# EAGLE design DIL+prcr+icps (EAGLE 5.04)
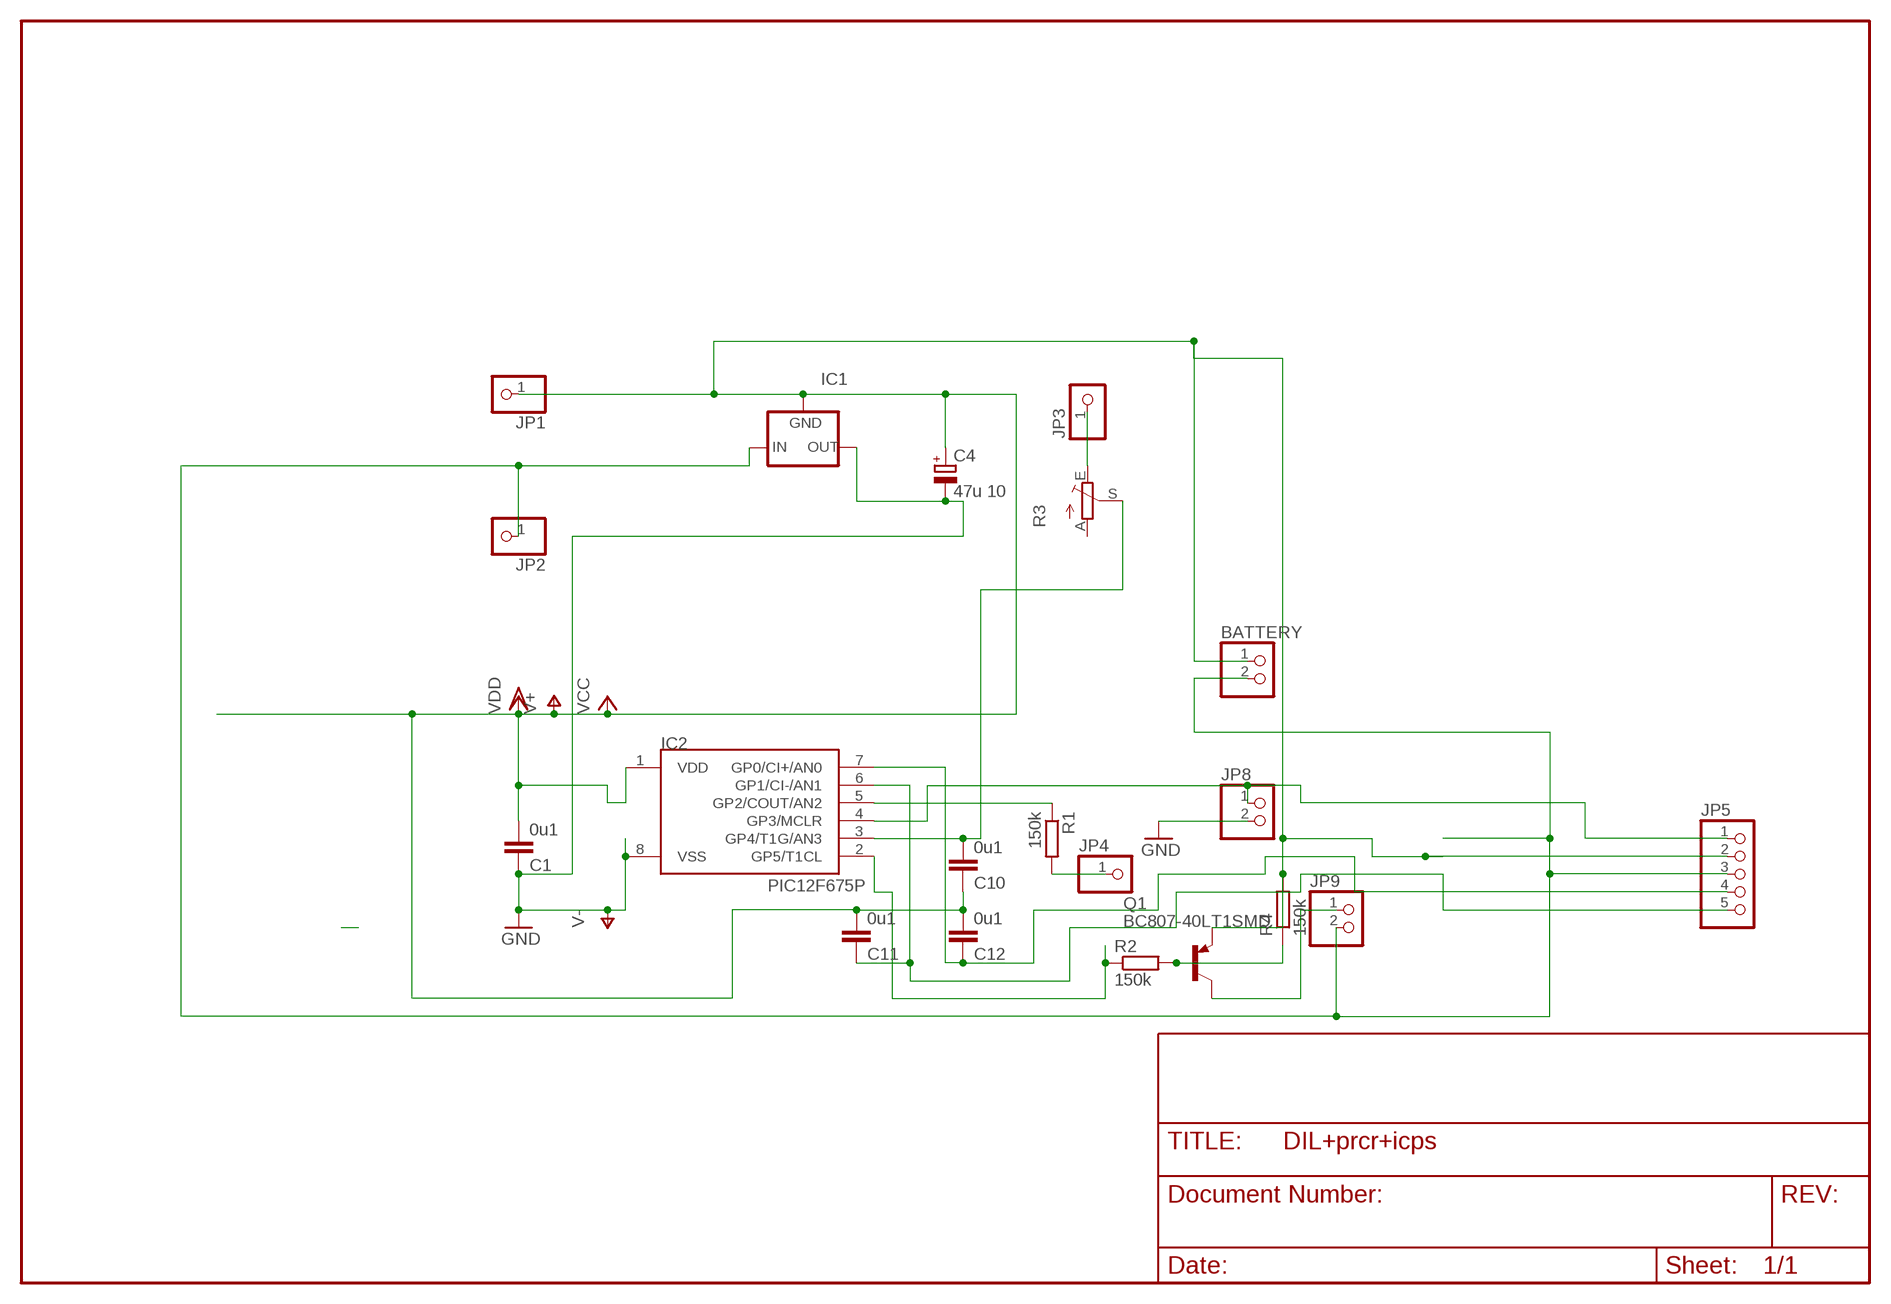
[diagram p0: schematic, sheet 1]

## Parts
BATTERY  PINHD-1X2  [1X02]
C1  0u1  C-EUC1206  [C1206]
C4  47u 10  CPOL-EUE2.5-6  [E2,5-6]
C10  0u1  C-EUC1206  [C1206]
C11  0u1  C-EUC1206  [C1206]
C12  0u1  C-EUC1206  [C1206]
IC1  79LXX  [79LXX]
IC2  PIC12F675P  [DIL8]
JP1  PINHD-1X1  [1X01]
JP2  PINHD-1X1  [1X01]
JP3  PINHD-1X1  [1X01]
JP4  PINHD-1X1  [1X01]
JP5  PINHD-1X5  [1X05]
JP8  PINHD-1X2  [1X02]
JP9  PINHD-1X2  [1X02]
Q1  BC807-40LT1SMD  [SOT23-BEC]
R1  150k  R-EU_R0805  [R0805]
R2  150k  R-EU_R0805  [R0805]
R3  TRIM_EU-CA6V  [CA6V]
R4  150k  R-EU_R0805  [R0805]

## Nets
GND: C1.1 C4.- IC1.OUT IC2.8(VSS) JP8.2 ; supply symbol labelled V-
N$1: JP3.1 R3.E
N$2: JP4.1 R1.2
N$3: IC2.4(GP3/MCLR) JP5.1 JP8.1
N$4: Q1.B R2.2 R4.1
N$5: IC2.5(GP2/COUT/AN2) R1.1
N$7: BATTERY.2 IC1.IN JP2.1 JP5.3 JP9.2
N$8: IC2.2(GP5/T1CL) R2.1
N$9: JP9.1 Q1.C
N$12: C10.2 IC2.3(GP4/T1G/AN3) R3.S
N$13: C12.1 IC2.7(GP0/CI+/AN0) JP5.4
N$15: C11.1 IC2.6(GP1/CI-/AN1) JP5.5
V+: BATTERY.1 C1.2 C4.+ C10.1 C11.2 C12.2 IC1.GND IC2.1(VDD) JP1.1 JP5.2 Q1.E R4.2 ; supply symbol labelled VCC, VDD
Unconnected: R3.A

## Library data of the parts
BATTERY JP8 JP9 = pinhead:PINHD-1X2: PIN HEADER
C1 C10-C12 = rcl:C-EU: CAPACITOR, European symbol
C4 = rcl:CPOL-EU: POLARIZED CAPACITOR, European symbol
IC1 = v-reg:79LXX: VOLTAGE REGULATOR
IC2 = microchip-3:PIC12F6*: uPC nW 1k Program Flash memory 2x Timer Comparator 10b A/D converter/ 4xIN
JP1-JP4 = pinhead:PINHD-1X1: PIN HEADER
JP5 = pinhead:PINHD-1X5: PIN HEADER
Q1 = transistor-pnp:BC807*: PNP Transistror
R1 R2 R4 = rcl:R-EU_: RESISTOR, European symbol
R3 = pot:TRIM_EU-: POTENTIOMETER

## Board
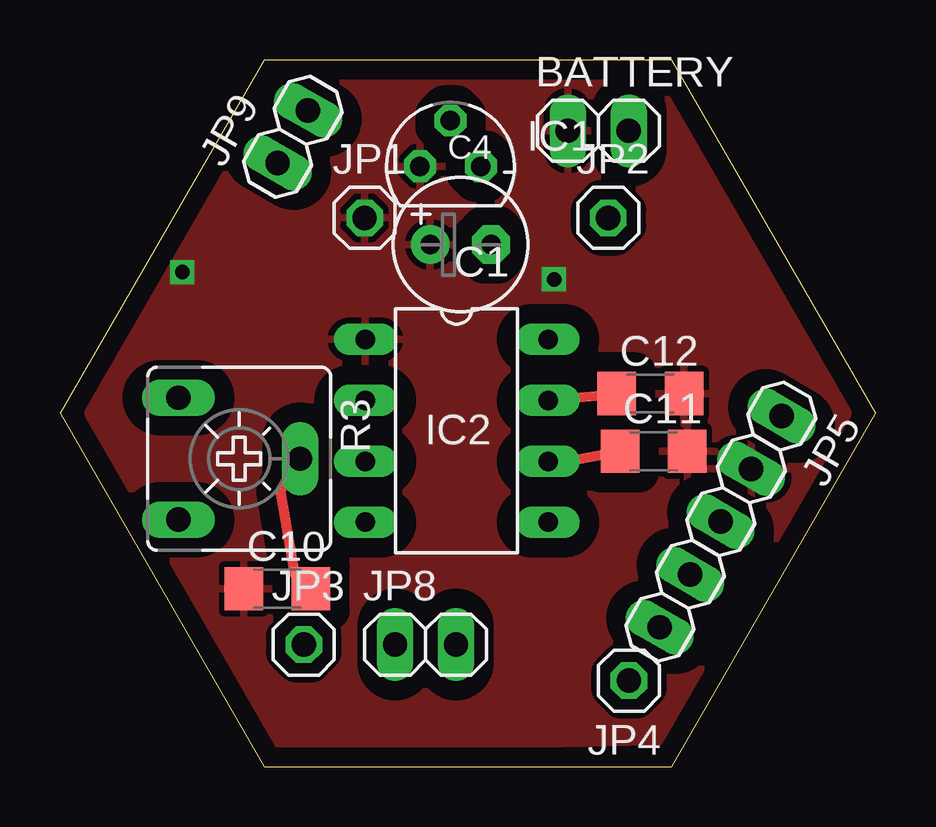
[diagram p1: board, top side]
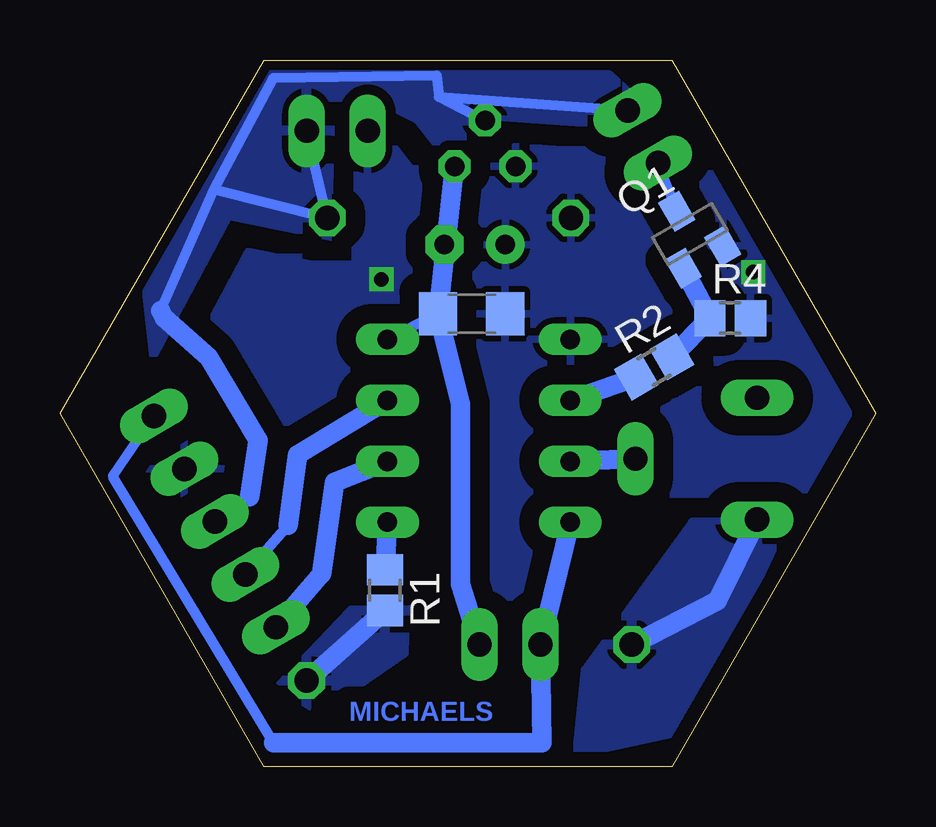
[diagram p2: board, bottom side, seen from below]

Size 34 x 29.44 mm. Coordinates in mm from the lower left corner, seen from the top.
Outline: 8.5,0 25.5,0 34,14.72 25.5,29.44 8.5,29.44 0,14.72 8.5,0
Copper layers (1*16): Top 0.035mm / dielectric 1.5mm / Bottom 0.035mm
Design rules "default *": minimum track width 10mil, minimum drill 24mil, track to track 8mil, track to pad 8mil, pad to pad 8mil, via to via 8mil, smd to smd 8mil, copper to edge 10mil, drill to drill 8mil, minimum pad ring 10mil, minimum via ring 8mil, stop-mask expansion 4mil, vias tented up to drill 0mil, thermal gap 10mil

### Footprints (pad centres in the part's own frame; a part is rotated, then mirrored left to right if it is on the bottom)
1X02 = drill 1.016 long: 1 -1.27,0; 2 1.27,0
C1206 = smd 1.6 x 1.8: 1 -1.4,0; 2 1.4,0
E2,5-6 = drill 0.813 pad 1.6 round: + -1.27,0 | drill 0.813 pad 1.6 octagon: - 1.27,0
79LXX = drill 0.813 octagon: GND -1.27,0; IN 0,1.905; OUT 1.27,0
DIL8 = drill 0.813 long: 1 -3.81,-3.81; 2 -1.27,-3.81; 3 1.27,-3.81; 4 3.81,-3.81; 5 3.81,3.81; 6 1.27,3.81; 7 -1.27,3.81; 8 -3.81,3.81
1X01 = drill 1.016 octagon: 1 0,0
1X05 = drill 1.016 long: 1 -5.08,0; 2 -2.54,0; 3 0,0; 4 2.54,0; 5 5.08,0
SOT23-BEC = smd 1 x 1.4: B -0.95,-1.1; C 0,1.1; E 0.95,-1.1
R0805 = smd 1.3 x 1.5: 1 -0.85,0; 2 0.85,0
CA6V = drill 1.016 long: A -2.54,-2.54; E 2.54,-2.54; S 0,2.54

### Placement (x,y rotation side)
BATTERY  22.44,26.49 0 top
C1  16.84,18.86 0 bottom
C4  16.7,21.75 0 top
C10  9.07,7.41 0 top
C11  24.75,13.14 0 top
C12  24.61,15.54 0 top
IC1  16.28,25.01 0 top
IC2  16.54,13.99 270 top
JP1  12.7,22.86 0 top
JP2  22.86,22.86 0 top
JP3  10.16,5.08 0 top
JP4  23.72,3.58 180 top
JP5  27.55,10.21 240 top
JP8  15.24,5.08 0 top
JP9  9.71,26.24 60 top
Q1  7.74,22.18 30 bottom
R1  20.45,7.35 270 bottom
R2  9.23,16.65 30 bottom
R3  7.47,12.83 270 top
R4  6.06,18.69 0 bottom

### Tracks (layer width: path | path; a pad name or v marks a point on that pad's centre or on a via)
GND
  Bottom 0.406: C1.1 IC2.8 | 18.07,20.35 C4.-
  Bottom 0.813: JP8.2 17.3,7.6 17.3,15.1 C1.1 18.07,20.35 IC1.OUT
N$1
  Bottom 0.813: JP3.1 6.6,6.9 R3.E
  pour Bottom (isolate 0.61): 5.08,10.16 7.62,10.16 12.1,4 12.45,0.55 7.85,1.55 3.7,10.35
N$2
  Bottom 0.813: JP4.1 R1.2
  pour Bottom (isolate 0.61): 22.86,2.54 19.65,4.75 19.6,6.65 21.85,6.5 24.85,3.35 23.3,2.4
N$3
  Bottom 0.406: JP5.1 31.8,12.1 25.1,1
  Bottom 0.813: IC2.4 JP8.1 13.9,1 25.1,1
N$4
  Bottom 0.813: Q1.B R4.1 R2.2
N$5
  Bottom 0.813: R1.1 IC2.5
N$7
  Bottom 0.406: 29.8,19 27.58,24.05 | 27.58,24.05 25.1,28.7 18.3,28.8 18.2,27.9 | 18.2,27.9 IC1.IN | 18.2,27.9 JP9.2 | 27.58,24.05 JP2.1 BATTERY.2 | 26.1,11.25 28,9.95 JP5.3
  Bottom 0.813: 29.8,19 29.65,18.7 27.8,17.05 25.75,13.6 26.1,11.25
  pour Bottom (isolate 0.406, rank 2): 10.16,27.94 11.1,28.8 25.2,29 30.45,20.35 30.1,17.2 27,23 22.6,22.1 22.8,24.1 22.7,27.9 20.9,27.9 19.1,27 18.2,25.85 16.9,25.85 17,27.2 11.3,26.8
N$8
  Bottom 0.813: R2.1 IC2.2
N$9
  Bottom 0.406: JP9.1 Q1.C
N$12
  Top 0.406: R3.S 9.2,11.5 9.8,8 C10.2
  Bottom 0.813: R3.S IC2.3
N$13
  Top 0.406: IC2.7 C12.1
  Bottom 0.406: 24.5,10.05 JP5.4
  Bottom 0.813: IC2.7 24.1,13 24.5,10.05
N$15
  Top 0.406: C11.1 21.13,12.73 IC2.6
  Bottom 0.813: IC2.6 22.55,11.85 23.1,8.04 JP5.5
V+  (via drill 0.6)
  other vias: 20.6,20.3 5.1,20.6
  pour Bottom (isolate 0.813, rank 4): 25.09,0.65 6.94,0.85 -0.63,14.71 7.94,28.25 23.9,28.98 28.25,24.24 33.14,13.91
  pour Top (isolate 0.813, rank 4): 25.05,28.74 33.52,14.83 25.59,1.05 7.24,0.65 -0.28,14.57 9.11,28.44

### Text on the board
Bottom: MICHAELS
